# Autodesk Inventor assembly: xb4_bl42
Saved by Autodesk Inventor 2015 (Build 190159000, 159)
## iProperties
Created: 2018-05
Part Number: xb4_bl42
Checked By: TraceParts S.A.
Catalog Web Link: www.traceparts.com
Document SubType Name: Assembly
Designer: TraceParts
Company: TraceParts S.A.
Author: TraceParts
REFERENCE: XB4 BL42
DESIGN: Unité de commande et de signalisation Ø 22 Harmony XB4 métallique - Bouton poussoir à impulsion sans marquage à poussoir dépassant - Produit complet, XB4 BL42
SUPPLIER: Schneider Electric
TraceParts.PartNumber: 10-24042009-073062
TraceParts.PartTitle: Unité de commande et de signalisation Ø 22 Harmony XB4 métallique - Bouton poussoir à impulsion sans marquage à poussoir dépassant - Produit complet
TraceParts.InstanceId: 10-24042009-0730627KTUEJMUBVTNMN3PDTAEN0SLW
TraceParts.PartStatus: Published
TraceParts.PartVersion: 1.1.4
TRACEPARTS: TRACEPARTS
TraceParts.PartLanguage: fr
TraceParts.ClassPath: SCHNEIDER_ELECTRIC:/F_SCHNEIDER/F_TELEMECANIQUE/F_TELEMECANIQUE.04/F_TELEMECANIQUE.04.010/F_TELEMECANIQUE.04.010.010/10-24042009-073062
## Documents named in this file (6)
- C:\TPO v2\SharedFS\Outgoing\xb4_bl42.iam
- C:\TPO v2\SharedFS\Outgoing\xb4_bl42_01.ipt
- C:\TPO v2\SharedFS\Outgoing\xb4_bl42_02.ipt
- C:\TPO v2\SharedFS\Outgoing\xb4_bl42_03.ipt
- C:\TPO v2\SharedFS\Outgoing\xb4_bl42_04.ipt
- C:\TPO v2\SharedFS\Outgoing\xb4_bl42_05.ipt
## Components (5 placed, 5 different names)
1. xb4_bl42_01:1
2. xb4_bl42_02:1
3. xb4_bl42_03:1
4. xb4_bl42_04:1
5. xb4_bl42_05:1
